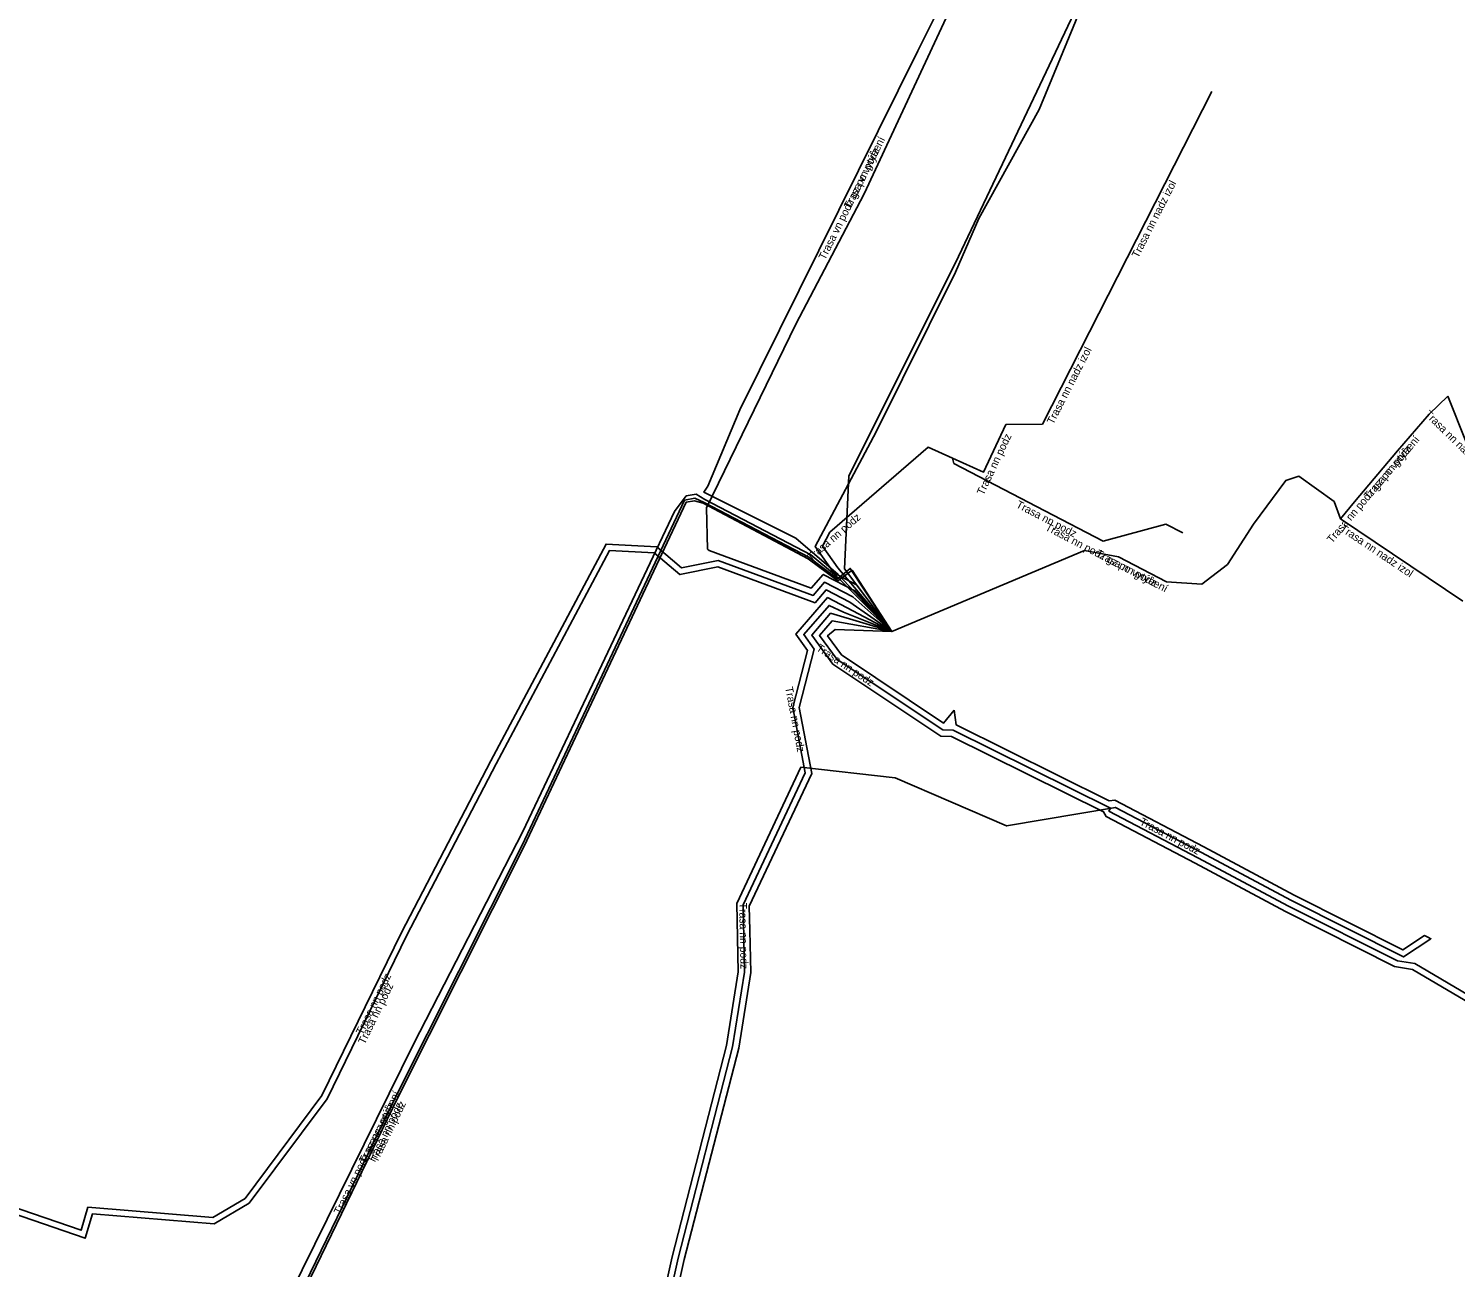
# Model space of a CAD drawing. Extents: x -528089 to -527692, y -1079306 to -1078676.
# Drawn here: x -528006 to -527914.1, y -1078937.8 to -1078858 of the extents above; entities that cross this region are included whole.
import ezdxf

# ---------------------------------------------------------------- set-up
doc = ezdxf.new("R2010")
doc.units = 0
for name, color, linetype in [('Popiskový text - Ostatní atributy Trasy', 7, 'Continuous'), ('Spojnice NN', 7, 'Continuous'), ('Spojnice VN', 7, 'Continuous')]:
    doc.layers.add(name, color=color, linetype=linetype)

msp = doc.modelspace()

# ---------------------------------------------------------------- linework, layer by layer
at = {"layer": 'Spojnice NN'}
for points in [[(-527876.15, -1078748.62), (-527881.08, -1078755.7), (-527890.34, -1078770.34), (-527895.52, -1078778.72), (-527901.44, -1078788.43), (-527903.84, -1078793.06), (-527907.78, -1078799.52), (-527916.61, -1078814.71), (-527917.06, -1078816.84), (-527919.98, -1078822.17), (-527924.47, -1078829.21), (-527929.52, -1078839.3), (-527933.49, -1078846.02), (-527936.34, -1078852.24), (-527940.87, -1078863.22), (-527944.75, -1078870.23), (-527946.26, -1078873.7), (-527951.36, -1078883.98), (-527955.295, -1078891.367), (-527954.103, -1078893.053), (-527952.625, -1078893.82), (-527950.354, -1078896.828)], [(-527950.354, -1078896.828), (-527952.689, -1078894.238), (-527954.779, -1078893.154), (-527955.547, -1078894.037), (-527962.128, -1078891.614), (-527962.23, -1078891.53), (-527962.29, -1078888.88), (-527956.54, -1078877.05), (-527952.15, -1078868.66), (-527944.96, -1078853.24), (-527938.27, -1078839.97), (-527934.2, -1078830.87), (-527931.28, -1078823.59), (-527931.84, -1078822.54), (-527939.45, -1078816.99), (-527943.96, -1078813.58), (-527953.39, -1078808.77), (-527964.38, -1078803), (-527974.88, -1078797.26), (-527982.7, -1078792.34), (-527984.36, -1078787.62), (-527987.11, -1078779.76), (-527987.28, -1078772), (-527986.995, -1078771.093)], [(-527936.418, -1078875.176), (-527929.75, -1078862.05)], [(-527940.665, -1078883.494), (-527936.418, -1078875.176)], [(-527921.47, -1078889.58), (-527920.57, -1078888.49), (-527917.79, -1078885.21), (-527915.75, -1078882.83), (-527914.54, -1078881.68)], [(-527921.47, -1078889.58), (-527920.57, -1078888.49), (-527917.79, -1078885.21), (-527915.75, -1078882.83), (-527914.54, -1078881.68)], [(-527909.343, -1078888.562), (-527913.372, -1078884.635), (-527914.54, -1078881.68)], [(-527940.665, -1078883.494), (-527943.006, -1078883.508), (-527944.46, -1078886.58), (-527946.455, -1078885.675)], [(-527946.455, -1078885.675), (-527948.01, -1078884.97), (-527954.351, -1078890.445), (-527954.827, -1078891.338), (-527953.835, -1078892.742), (-527950.354, -1078896.828)], [(-527931.611, -1078890.485), (-527932.709, -1078889.931), (-527936.755, -1078891.028), (-527946.367, -1078886.015), (-527946.455, -1078885.675)], [(-527950.354, -1078896.828), (-527937.95, -1078891.62), (-527935.77, -1078892.02), (-527932.66, -1078893.64), (-527930.39, -1078893.78), (-527928.75, -1078892.51), (-527927.06, -1078889.92), (-527924.99, -1078887.12), (-527924.15, -1078886.84), (-527921.88, -1078888.47), (-527921.47, -1078889.58)], [(-527950.354, -1078896.828), (-527937.95, -1078891.62), (-527935.77, -1078892.02), (-527932.66, -1078893.64), (-527930.39, -1078893.78), (-527928.75, -1078892.51), (-527927.06, -1078889.92), (-527924.99, -1078887.12), (-527924.15, -1078886.84), (-527921.88, -1078888.47), (-527921.47, -1078889.58)], [(-527950.354, -1078896.828), (-527953.033, -1078892.769), (-527953.865, -1078893.434), (-527955.71, -1078892.04), (-527962.44, -1078888.52), (-527963.051, -1078888.256), (-527963.713, -1078888.376), (-527974.175, -1078910.594), (-527982.325, -1078926.824), (-527989.864, -1078942.373), (-527997.603, -1078957.621), (-528002.414, -1078966.82), (-528002.07, -1078967.65), (-527991.84, -1078972.17), (-527986.771, -1078974.84)], [(-527950.354, -1078896.828), (-527952.922, -1078892.893), (-527953.84, -1078893.57), (-527955.74, -1078892.15), (-527962.51, -1078888.58), (-527963.06, -1078888.41), (-527963.61, -1078888.51), (-527974.04, -1078910.66), (-527982.19, -1078926.89), (-527989.73, -1078942.44), (-527997.47, -1078957.69), (-528002.25, -1078966.83), (-528002.01, -1078967.46), (-527992.25, -1078971.87), (-527986.953, -1078974.549)], [(-527921.47, -1078889.58), (-527913.576, -1078894.886)], [(-528025.255, -1078927.652), (-528024.997, -1078927.114), (-528024.288, -1078926.581), (-528014.768, -1078930.578), (-528010.294, -1078932.745), (-528002.573, -1078935.393), (-528002.136, -1078933.917), (-527994.097, -1078934.575), (-527992.016, -1078933.338), (-527987.062, -1078926.725), (-527981.949, -1078916.21), (-527976.187, -1078905.167), (-527968.767, -1078891.203), (-527965.502, -1078891.384), (-527963.895, -1078892.735), (-527961.535, -1078892.258), (-527955.425, -1078894.508), (-527954.685, -1078893.653), (-527952.874, -1078894.592), (-527950.354, -1078896.828)], [(-528025.255, -1078927.652), (-528024.839, -1078927.496), (-528024.232, -1078927.039), (-528014.932, -1078930.942), (-528010.446, -1078933.115), (-528002.307, -1078935.907), (-528001.844, -1078934.343), (-527994.003, -1078934.985), (-527991.744, -1078933.642), (-527986.718, -1078926.935), (-527981.591, -1078916.39), (-527975.833, -1078905.353), (-527968.533, -1078891.617), (-527965.658, -1078891.776), (-527964.005, -1078893.165), (-527961.569, -1078892.673), (-527955.304, -1078894.979), (-527954.588, -1078894.153), (-527953.057, -1078894.947), (-527950.354, -1078896.828)], [(-527967.66, -1078953.06), (-527964.12, -1078937.19), (-527960.61, -1078923.58), (-527959.85, -1078918.77), (-527959.94, -1078914.43), (-527955.935, -1078905.928), (-527956.735, -1078901.723), (-527955.791, -1078898.05), (-527956.54, -1078897.016), (-527954.493, -1078894.654), (-527953.242, -1078895.303), (-527950.354, -1078896.828)], [(-527959.506, -1078916.086), (-527959.538, -1078914.515), (-527955.518, -1078905.982), (-527956.325, -1078901.737), (-527955.356, -1078897.967), (-527956.03, -1078897.038), (-527954.397, -1078895.155), (-527953.479, -1078895.6), (-527950.354, -1078896.828)], [(-527950.354, -1078896.828), (-527954.301, -1078895.655), (-527955.519, -1078897.061), (-527954.162, -1078898.933), (-527947.2, -1078903.574), (-527946.507, -1078903.595), (-527936.72, -1078908.45), (-527936.559, -1078908.751), (-527930.831, -1078911.761), (-527924.996, -1078914.873), (-527917.977, -1078918.408), (-527916.815, -1078918.598), (-527910.04, -1078922.589), (-527903.801, -1078925.229), (-527899.804, -1078916.808), (-527898.093, -1078915.123), (-527891.727, -1078912.006), (-527882.341, -1078916.059), (-527871.963, -1078922.152), (-527865.931, -1078925.817), (-527860.158, -1078929.989)], [(-527950.354, -1078896.828), (-527954.205, -1078896.155), (-527955.009, -1078897.082), (-527953.88, -1078898.64), (-527947.074, -1078903.178), (-527946.408, -1078903.198), (-527936.279, -1078908.221), (-527936.373, -1078908.397), (-527930.644, -1078911.407), (-527924.812, -1078914.518), (-527917.797, -1078918.051), (-527916.677, -1078918.215), (-527909.86, -1078922.231)], [(-527946.339, -1078901.891), (-527947.025, -1078902.729), (-527953.598, -1078898.347), (-527954.498, -1078897.105), (-527954.016, -1078896.703), (-527950.354, -1078896.828)], [(-527915.84, -1078916.52), (-527916.044, -1078916.415), (-527917.438, -1078917.335), (-527924.444, -1078913.807), (-527930.269, -1078910.699), (-527936.001, -1078907.689), (-527936.36, -1078907.73), (-527946.207, -1078902.851), (-527946.339, -1078901.891)], [(-527915.84, -1078916.52), (-527915.636, -1078916.625), (-527917.411, -1078917.796), (-527924.628, -1078914.162), (-527930.456, -1078911.053), (-527935.955, -1078908.165), (-527942.97, -1078909.36), (-527950.15, -1078906.25), (-527956.21, -1078905.573), (-527960.342, -1078914.344), (-527960.251, -1078918.743), (-527961.002, -1078923.499), (-527964.509, -1078937.096), (-527968.037, -1078952.914)], [(-527959.506, -1078916.086), (-527959.45, -1078918.798)], [(-527959.45, -1078918.798), (-527960.218, -1078923.662), (-527963.731, -1078937.283), (-527967.282, -1078953.205), (-527969.775, -1078957.593), (-527972.108, -1078973.015), (-527971.767, -1078973.909), (-527965.354, -1078976.633), (-527959.902, -1078978.262), (-527958.774, -1078976.836), (-527957.385, -1078971.683), (-527956.185, -1078965.938), (-527957.378, -1078965.225), (-527957.33, -1078965.02)]]:
    msp.add_lwpolyline(points, dxfattribs=at)
at = {"layer": 'Spojnice VN'}
for points in [[(-527950.354, -1078896.828), (-527953.403, -1078892.802), (-527953.13, -1078886.8), (-527946.25, -1078873.1), (-527936.41, -1078852.32), (-527930.88, -1078841.27), (-527920.34, -1078822.02), (-527916.96, -1078814.57), (-527906.15, -1078795.86), (-527889.87, -1078769.33), (-527884.73, -1078761.54), (-527875.38, -1078747), (-527869.33, -1078736.87), (-527867.99, -1078733.54), (-527866.55, -1078732.38)], [(-527950.354, -1078896.828), (-527953.403, -1078892.802), (-527953.13, -1078886.8), (-527946.25, -1078873.1), (-527936.41, -1078852.32), (-527930.88, -1078841.27), (-527920.34, -1078822.02), (-527916.96, -1078814.57), (-527906.15, -1078795.86), (-527889.87, -1078769.33), (-527884.73, -1078761.54), (-527875.38, -1078747), (-527869.33, -1078736.87), (-527867.99, -1078733.54), (-527866.55, -1078732.38)], [(-527935.37, -1078831.45), (-527938.69, -1078839.37), (-527943.3, -1078848.64), (-527948.68, -1078859.44), (-527960.15, -1078882.56), (-527962.22, -1078887.48), (-527962.47, -1078887.86), (-527956.55, -1078890.83), (-527953.82, -1078893.17), (-527950.354, -1078896.828)], [(-527935.37, -1078831.45), (-527938.69, -1078839.37), (-527943.3, -1078848.64), (-527948.68, -1078859.44), (-527960.15, -1078882.56), (-527962.22, -1078887.48), (-527962.47, -1078887.86), (-527956.55, -1078890.83), (-527953.82, -1078893.17), (-527950.354, -1078896.828)], [(-527987.518, -1078974.53), (-527987.52, -1078974.529), (-527995.49, -1078970.73), (-528002.17, -1078968.08), (-528002.78, -1078966.87), (-527989.93, -1078941.16), (-527981.15, -1078923.37), (-527974.13, -1078909.71), (-527964.35, -1078889.11), (-527963.6, -1078888.1), (-527962.96, -1078887.99), (-527962.4, -1078888.34), (-527955.58, -1078891.9), (-527953.929, -1078893.274), (-527950.354, -1078896.828)], [(-527987.518, -1078974.53), (-527987.52, -1078974.529), (-527995.49, -1078970.73), (-528002.17, -1078968.08), (-528002.78, -1078966.87), (-527989.93, -1078941.16), (-527981.15, -1078923.37), (-527974.13, -1078909.71), (-527964.35, -1078889.11), (-527963.6, -1078888.1), (-527962.96, -1078887.99), (-527962.4, -1078888.34), (-527955.58, -1078891.9), (-527953.929, -1078893.274), (-527950.354, -1078896.828)]]:
    msp.add_lwpolyline(points, dxfattribs=at)

# ---------------------------------------------------------------- texts
at = {"layer": 'Popiskový text - Ostatní atributy Trasy'}
for s, rotation, p in [('Trasa vn podz gz po vytýèení', 63.61366, (-527954.657, -1078872.951)), ('Trasa vn podz', 63.61366, (-527953.019, -1078869.65)), ('Trasa nn nadz izol', 63.06946, (-527934.492, -1078872.821)), ('Trasa nn nadz izol', 62.95141, (-527939.959, -1078883.54)), ('Trasa nn nadz izol', 315.73457, (-527916.093, -1078882.891)), ('Trasa nn podz', 64.67347, (-527944.46, -1078888.099)), ('Trasa nn podz gz po vytýèení', 49.71669, (-527922.006, -1078891.189)), ('Trasa nn podz', 49.71669, (-527919.623, -1078888.378)), ('Trasa nn podz', 332.4542, (-527942.404, -1078888.815)), ('Trasa nn podz', 40.80826, (-527955.557, -1078892.345)), ('Trasa nn podz gz po vytýèení', 332.48498, (-527940.523, -1078890.277)), ('Trasa nn nadz izol', 326.09399, (-527921.529, -1078890.324)), ('Trasa nn podz', 332.48498, (-527937.255, -1078891.98)), ('Trasa nn podz', 326.30993, (-527955.265, -1078898.017)), ('Trasa nn podz', 280.76383, (-527957.232, -1078900.443)), ('Trasa nn podz', 332.29504, (-527934.442, -1078909.242)), ('Trasa nn podz', 271.17776, (-527960.193, -1078914.308)), ('Trasa nn podz', 64.0683, (-527984.452, -1078922.844)), ('Trasa nn podz', 64.07089, (-527984.306, -1078923.461)), ('Trasa vn podz gz po vytýèení', 63.73202, (-527985.88, -1078934.422)), ('Trasa vn podz', 63.73202, (-527984.249, -1078931.117)), ('Trasa nn podz', 64.13337, (-527983.697, -1078931.145)), ('Trasa nn podz', 64.13184, (-527983.496, -1078931.073))]:
    msp.add_text(s, height=0.5, rotation=rotation, dxfattribs=at).set_placement(p)

doc.saveas('drawing.dxf')
